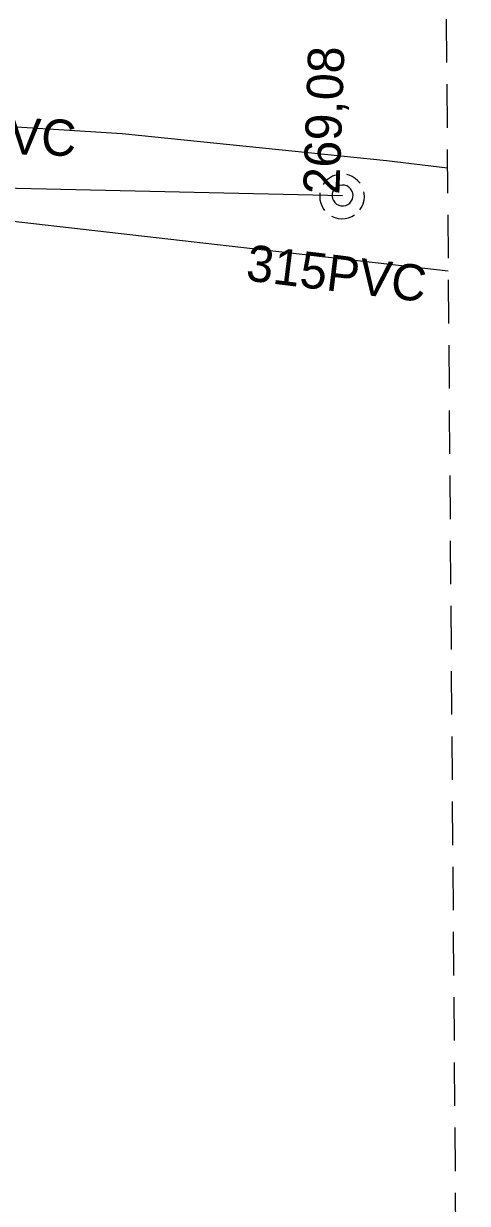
# Model space of a CAD drawing. Extents: x -732074 to -731966, y -1048695 to -1047982.
# Drawn here: x -731976.2 to -731966.41, y -1048660.19 to -1048634.13 of the extents above; entities that cross this region are included whole.
import ezdxf

# ---------------------------------------------------------------- set-up
doc = ezdxf.new("R2010")
doc.units = 0
doc.header["$LTSCALE"] = 0.32
doc.linetypes.add('MEDIUM_DASHED', pattern=[4.5, 3, -1.5])
doc.layers.add('1', color=7, linetype='Continuous')
for name, color, linetype, lineweight in [('18', 7, 'Continuous', 13), ('20', 7, 'Continuous', 13), ('63', 7, 'MEDIUM_DASHED', 25), ('8', 7, 'Continuous', 13)]:
    doc.layers.add(name, color=color, linetype=linetype, lineweight=lineweight)

msp = doc.modelspace()

# ---------------------------------------------------------------- linework, layer by layer
at = {"layer": '18'}
for points in [[(-731969.313, -1048637.477), (-731969.384, -1048637.505), (-731969.451, -1048637.544), (-731969.511, -1048637.592), (-731969.562, -1048637.649), (-731969.586, -1048637.683)], [(-731968.772, -1048637.66), (-731968.822, -1048637.602), (-731968.88, -1048637.552), (-731968.945, -1048637.511), (-731969.016, -1048637.482), (-731969.065, -1048637.468)], [(-731969.658, -1048637.869), (-731969.664, -1048637.946), (-731969.659, -1048638.023), (-731969.642, -1048638.098), (-731969.613, -1048638.169), (-731969.573, -1048638.235), (-731969.557, -1048638.257)], [(-731968.777, -1048638.246), (-731968.736, -1048638.181), (-731968.705, -1048638.111), (-731968.686, -1048638.036), (-731968.678, -1048637.96), (-731968.683, -1048637.883), (-731968.689, -1048637.848)], [(-731969.4, -1048638.386), (-731969.33, -1048638.417), (-731969.255, -1048638.436), (-731969.179, -1048638.443), (-731969.102, -1048638.438), (-731969.027, -1048638.421), (-731968.955, -1048638.393), (-731968.895, -1048638.358)]]:
    msp.add_lwpolyline(points, dxfattribs=at)
msp.add_lwpolyline([(-731968.929, -1048637.929), (-731968.935, -1048637.877), (-731968.953, -1048637.827), (-731968.981, -1048637.783), (-731969.019, -1048637.746), (-731969.064, -1048637.719), (-731969.114, -1048637.703), (-731969.166, -1048637.698), (-731969.218, -1048637.705), (-731969.267, -1048637.724), (-731969.311, -1048637.754), (-731969.346, -1048637.793), (-731969.372, -1048637.838), (-731969.387, -1048637.889), (-731969.39, -1048637.941), (-731969.382, -1048637.993), (-731969.361, -1048638.041), (-731969.331, -1048638.084), (-731969.291, -1048638.119), (-731969.245, -1048638.143), (-731969.194, -1048638.157), (-731969.142, -1048638.159), (-731969.09, -1048638.149), (-731969.042, -1048638.127), (-731969, -1048638.095), (-731968.967, -1048638.055), (-731968.943, -1048638.008), (-731968.931, -1048637.957)], close=True, dxfattribs=at)
at = {"layer": '20'}
for points in [[(-731969.16, -1048637.94), (-731982.899, -1048637.629), (-731984.98, -1048611.47)], [(-731969.16, -1048637.94), (-731982.899, -1048637.629), (-731984.98, -1048611.47)], [(-731966.829, -1048639.601), (-731976.76, -1048638.47), (-731984.62, -1048638.44)], [(-731966.829, -1048639.601), (-731976.76, -1048638.47), (-731984.62, -1048638.44)]]:
    msp.add_lwpolyline(points, dxfattribs=at)
at = {"layer": '63'}
msp.add_lwpolyline([(-731967.071, -1048608.115), (-731966.405, -1048694.807), (-731966.405, -1048694.809), (-731966.406, -1048694.811), (-731966.407, -1048694.813), (-731966.408, -1048694.814), (-731966.409, -1048694.816), (-731966.411, -1048694.817), (-731966.413, -1048694.817), (-731966.415, -1048694.818), (-731966.417, -1048694.817), (-731995.356, -1048690.903), (-731995.358, -1048690.903), (-731995.36, -1048690.902), (-731995.362, -1048690.901), (-731995.363, -1048690.899), (-731995.364, -1048690.897), (-731995.365, -1048690.895), (-731995.365, -1048690.893), (-731995.541, -1048612.001)], dxfattribs=at)
at = {"layer": '8', "lineweight": 25}
msp.add_lwpolyline([(-731978.579, -1048636.27), (-731974.02, -1048636.56), (-731968.19, -1048637.159), (-731966.847, -1048637.321)], dxfattribs=at)

# ---------------------------------------------------------------- texts
at = {"layer": '1'}
for s, rotation, p in [('269,08', 88, (-731969.231, -1048637.918)), ('315PVC', 358, (-731979.032, -1048636.925)), ('315PVC', 353, (-731971.316, -1048639.801))]:
    msp.add_text(s, height=0.8, rotation=rotation, dxfattribs=at).set_placement(p)

doc.saveas('drawing.dxf')
